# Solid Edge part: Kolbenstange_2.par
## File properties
Username: bmolnar
Dokumentum tartalom típus: 0
Author: bmolnar
Last saved by: bmolnar
Revision: 94
Sűrűség: 0,000 kg/m^3
Pontosság: 0,990
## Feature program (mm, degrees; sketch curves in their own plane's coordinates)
base feature "unnamed BaseFeature 1"
thread "unnamed Thread 1"
chamfer "Letörés_1"  SetBackValue2 = 20 deg
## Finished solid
Body 1: solid body, 19 faces, 31 edges, 16 vertices.
  Faces by surface: plane 8, cylinder 5, cone 3, torus 3
  Edges by curve: circle 18, line 8, curve on surface 3, ellipse 2
Bounding box of the edges (mm; curved faces can reach further): 100.000 x 100.000 x 1632.500, from (-50, -50, -78.75) to (50, 50, 1553.75).
Cylindrical faces by radius (mm): R8.75 x1, R10 x1, R12.25 x1, R12.5 x1, R50 x1
Conical faces (half-angle, radius in mm at the cone's reference point): 20 deg R8.7989 x1, 30 deg R12.375 x1, 60 deg R9.375 x1
Toroidal faces (ring radius, tube radius in mm): R9.15 r0.4 x2, R10.45 r1.8 x1
Planar faces by outward normal: +x 1, +z 3, -x 1, -z 1, oblique 2
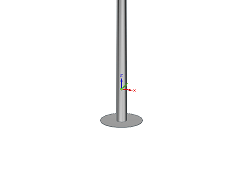
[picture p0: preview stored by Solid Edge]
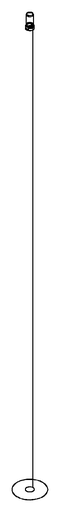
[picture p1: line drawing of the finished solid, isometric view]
